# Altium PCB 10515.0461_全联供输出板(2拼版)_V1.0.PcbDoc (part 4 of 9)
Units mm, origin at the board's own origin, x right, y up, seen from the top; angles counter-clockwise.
Board outline 283.88 x 134.8 mm, 2 copper layers (Top Layer, Bottom Layer); 298 components, 0 nets, 1264 pads, 970 vias.
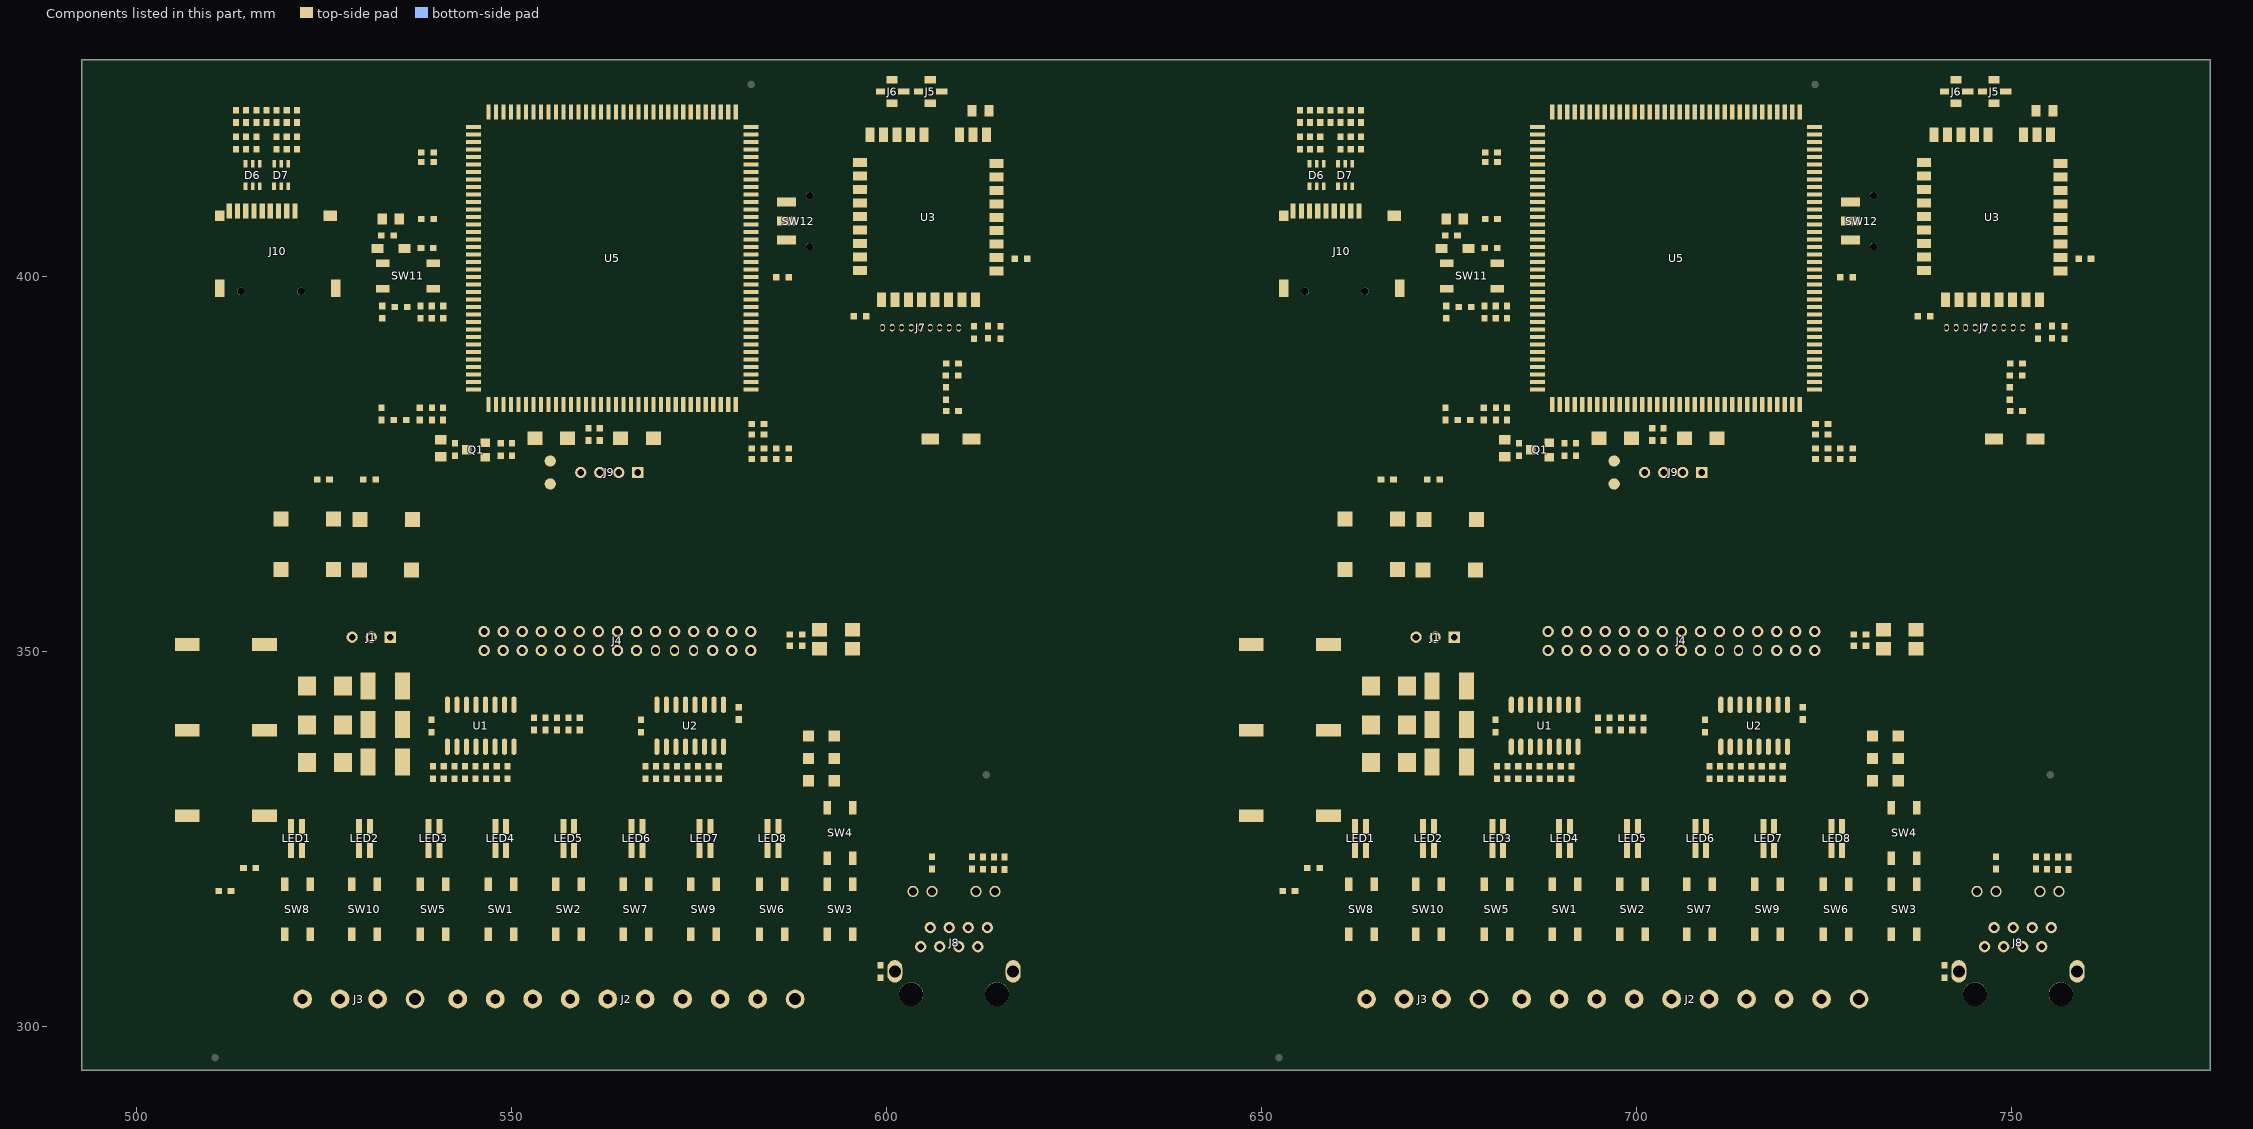
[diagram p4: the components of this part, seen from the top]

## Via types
v1: diameter 0.7, hole 0.4, Top Layer to Bottom Layer, tented both sides, 970 vias

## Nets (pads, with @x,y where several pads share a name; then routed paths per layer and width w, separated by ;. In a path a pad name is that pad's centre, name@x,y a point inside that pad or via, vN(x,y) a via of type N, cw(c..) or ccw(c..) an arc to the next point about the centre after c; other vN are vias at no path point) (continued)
copper on no net: (continued)
  Top Layer w0.3: 724.578,385.822 cw(c724.792,385.608) 724.792,385.91 cw(c724.792,386.212) 724.578,385.998 ; 724.578,386.822 cw(c724.792,386.608) 724.792,386.91 cw(c724.792,387.212) 724.578,386.998 ; 724.578,388.822 cw(c724.792,388.608) 724.792,388.91 cw(c724.792,389.212) 724.578,388.998 ; 724.578,389.822 cw(c724.792,389.608) 724.792,389.91 cw(c724.792,390.212) 724.578,389.998 ; 724.578,399.822 cw(c724.792,399.608) 724.792,399.91 cw(c724.792,400.212) 724.578,399.998 ; 724.578,406.822 cw(c724.792,406.608) 724.792,406.91 cw(c724.792,407.212) 724.578,406.998 ; 724.578,407.822 cw(c724.792,407.608) 724.792,407.91 cw(c724.792,408.212) 724.578,407.998 ; 724.677,303.604 724.677,305.94 725.084,306.347 733.247,306.347 735.273,308.373 739.083,308.373 741.016,310.306 741.016,336.751 740.508,337.259 731.815,337.259 731.46,337.614 ; 725.528,378.915 731.561,378.915 731.95,378.526 731.95,356.436 ; 725.528,380.312 731.815,380.312 732.577,379.55 732.577,355.547 ; 725.748,378.734 cw(c726.186,378.296) 726.186,378.915 cw(c726.186,379.534) 725.748,379.096 ; 725.748,380.131 cw(c726.186,379.693) 726.186,380.312 cw(c726.186,380.931) 725.748,380.493 ; 725.796,327.393 ccw(c725.369,327.82) 725.973,327.82 ccw(c726.577,327.82) 726.15,327.393 ; 726.426,399.91 cw(c726.426,399.154) 726.96,399.689 ; v1(726.611,312.243) 728.327,312.243 ; 726.619,399.91 ccw(c726.619,400.392) 726.96,400.051 ; v1@726.752,312.101 cw(c727.094,311.76) 727.094,312.243 cw(c727.094,312.726) v1@726.752,312.384 ; 727.256,327.368 ccw(c726.829,327.795) 727.433,327.795 ccw(c728.037,327.795) 727.61,327.368 ; 727.525,404.505 ccw(c726.757,403.737) 726.757,404.823 ccw(c726.757,405.909) 727.525,405.141 ; 727.525,409.585 ccw(c726.757,408.817) 726.757,409.903 ccw(c726.757,410.989) 727.525,410.221 ; 728.08,311.995 ccw(c727.482,311.398) 727.482,312.243 ccw(c727.482,313.088) 728.08,312.49 ; 728.479,350.277 ccw(c728.035,350.721) 728.663,350.721 ; 728.488,350.286 cw(c728.919,349.855) 728.919,350.465 ; 728.513,407.363 730.291,407.363 730.672,406.982 730.672,400.124 730.418,399.87 728.83,399.87 ; 729.05,399.689 cw(c729.488,399.251) 729.488,399.87 cw(c729.488,400.489) 729.05,400.051 ; 729.161,304.576 ccw(c728.707,305.433) 729.677,305.433 ; 729.302,304.311 ccw(c728.971,304.934) 729.677,304.934 ccw(c730.383,304.934) 730.052,304.311 ; 729.501,407.045 cw(c730.269,406.277) 730.269,407.363 cw(c730.269,408.449) 729.501,407.681 ; v1@729.642,377.758 ccw(c729.3,377.416) 729.3,377.899 ccw(c729.3,378.382) v1@729.642,378.04 ; 729.677,303.604 729.677,305.433 ; 730.193,304.576 cw(c730.647,305.433) 729.677,305.433 ; v1@730.72,390.678 753.532,390.678 754.119,390.678 754.421,390.98 754.421,393.33 ; v1@730.813,390.585 cw(c731.038,390.36) 731.038,390.678 ; v1@730.813,390.867 ccw(c731.272,391.326) 731.272,390.678 ; 731.148,338.169 cw(c730.811,337.614) 731.46,337.614 ; 731.207,332.168 cw(c731.023,331.772) 731.46,331.772 ; v1@731.42,355.66 ccw(c731.078,355.318) 731.078,355.801 ccw(c731.078,356.284) v1@731.42,355.942 ; v1@731.426,355.92 731.434,355.92 731.95,356.436 ; 731.46,332.712 731.46,331.772 ; 731.46,338.681 731.46,337.614 ; v1@731.546,356 ccw(c731.513,356.436) 731.95,356.436 ; v1@731.568,355.701 ccw(c731.538,356.113) 731.95,356.113 ; v1@731.627,355.99 ccw(c731.73,356.283) 731.95,356.063 ; 731.713,332.168 ccw(c731.896,331.772) 731.46,331.772 ; v1@731.758,355.834 cw(c732.436,355.95) 731.95,356.436 ; 731.772,338.169 ccw(c732.109,337.614) 731.46,337.614 ; 732.536,354.277 732.536,354.445 732.069,354.912 732.577,355.42 732.577,355.547 ; 732.577,354.912 732.577,355.547 ; 734.889,335.697 739.992,335.697 ; 734.889,338.681 736.108,338.681 ; 735.313,332.288 cw(c736.337,331.264) 736.337,332.712 cw(c736.337,334.161) 735.313,333.137 ; 735.313,335.273 cw(c736.337,334.248) 736.337,335.697 cw(c736.337,337.145) 735.313,336.121 ; 735.364,338.316 cw(c736.108,337.744) 736.108,338.681 ; 735.364,339.047 ccw(c736.108,339.619) 736.108,338.681 ; v1@735.484,392.518 ccw(c735.142,392.86) 735.625,392.86 ccw(c736.108,392.86) v1@735.766,392.518 ; v1(735.625,392.377) 735.625,403.807 736.189,404.371 738.336,404.371 ; 736.309,393.483 cw(c736.486,393.185) 736.731,393.43 ; v1@736.463,393.225 cw(c736.69,392.844) 737.003,393.158 ; 736.474,393.687 cw(c736.075,393.289) v1@736.609,393.107 ; v1@736.627,332.571 ccw(c736.285,332.23) 736.285,332.712 ccw(c736.285,333.195) v1@736.627,332.854 ; v1@736.63,393.302 cw(c736.967,393.774) 736.387,393.774 ; v1@736.655,392.998 cw(c736.997,392.656) 736.997,393.139 cw(c736.997,393.622) v1@736.655,393.28 ; v1@736.909,332.571 cw(c737.251,332.23) 737.251,332.712 cw(c737.251,333.195) v1@736.909,332.854 ; 737.276,393.139 737.022,393.139 736.387,393.774 ; 737.329,394.844 ccw(c736.891,395.282) 737.51,395.282 ccw(c738.13,395.282) 737.692,394.844 ; v1@737.389,395.411 cw(c737.094,395.116) 737.51,395.116 ; v1@737.389,395.693 ccw(c737.094,395.988) 737.51,395.988 ; 737.51,394.663 737.51,399.945 738.336,400.771 ; 737.51,395.022 cw(c738.06,395.022) v1@737.671,395.411 ; 737.51,396.082 ccw(c738.06,396.082) v1@737.671,395.693 ; 737.668,402.253 ccw(c736.9,401.485) 736.9,402.571 ccw(c736.9,403.657) 737.668,402.889 ; 737.668,404.053 ccw(c736.9,403.285) 736.9,404.371 ccw(c736.9,405.457) 737.668,404.689 ; 738.336,402.571 736.802,402.571 736.387,402.156 736.387,393.774 ; 739.054,335.697 ccw(c739.054,336.31) v1@739.488,335.876 ; 739.161,394.663 741.34,394.663 ; 739.238,335.697 cw(c739.238,335.344) v1@739.488,335.594 ; 739.381,394.482 cw(c739.819,394.044) 739.819,394.663 cw(c739.819,395.282) 739.381,394.844 ; v1@739.744,335.571 cw(c739.927,335.307) 740.154,335.535 ; v1@739.778,335.601 cw(c739.992,335.409) 739.992,335.697 ; v1@739.813,335.815 ccw(c739.992,335.893) 739.992,335.697 ; 740.868,396.203 cw(c740.1,395.435) 741.186,395.435 cw(c742.272,395.435) 741.504,396.203 ; 741.042,308.151 cw(c741.612,308.151) 741.209,308.553 ; 741.086,308.407 ccw(c741.086,309.118) 741.589,308.615 ; 741.186,396.871 741.186,394.817 741.34,394.663 ; 741.219,306.719 ccw(c741.432,307.068) 741.721,306.779 ; 741.234,393.033 ccw(c740.978,392.777) 740.978,393.139 ccw(c740.978,393.501) 741.234,393.245 ; 741.267,306.28 cw(c741.705,305.842) 741.705,306.462 cw(c741.705,307.081) 741.267,306.643 ; 741.339,306.456 cw(c741.721,306.391) 741.721,306.779 ; 741.34,393.139 v1@736.768,393.139 ; 741.403,306.779 741.721,306.779 ; 741.497,308.523 ccw(c741.869,308.151) 741.342,308.151 cw(c742.636,308.151) 741.721,309.065 ; 741.749,306.807 cw(c742.386,306.169) 743.009,306.821 ; 741.755,306.496 cw(c742.342,305.908) 742.828,306.582 ; 741.966,307.024 cw(c742.598,306.391) 743.216,307.038 ; 742.126,306.841 cw(c741.721,306.867) 741.721,306.462 ; 742.227,307.285 741.721,306.779 ; 742.316,393.687 cw(c741.967,393.339) 742.46,393.339 ; 742.356,309.383 741.086,308.113 741.086,308.43 742.102,309.446 744.388,309.446 744.642,309.192 750.865,309.192 751.504,309.831 751.504,310.585 ; 742.367,306.19 ccw(c741.721,305.558) 741.721,306.462 ; 742.61,393.139 742.61,393.393 741.34,394.663 ; 742.661,396.202 cw(c741.899,395.437) 742.979,395.437 ; 742.979,396.871 742.979,395.437 ; 743.297,396.202 ccw(c744.059,395.437) 742.979,395.437 ; 743.774,393.445 ccw(c743.518,393.701) 743.88,393.701 ccw(c744.242,393.701) 743.986,393.445 ; 743.88,393.139 743.88,394.536 742.979,395.437 ; 744.454,396.203 cw(c743.685,395.435) 744.772,395.435 cw(c745.858,395.435) 745.09,396.203 ; 744.772,396.871 744.772,395.295 745.15,394.917 745.15,393.139 ; 745.044,393.445 ccw(c744.788,393.701) 745.15,393.701 ccw(c745.512,393.701) 745.256,393.445 ; 746.246,396.203 cw(c745.827,395.784) 746.42,395.784 ; 746.314,393.445 ccw(c746.058,393.701) 746.42,393.701 ccw(c746.782,393.701) 746.526,393.445 ; 746.42,393.139 746.42,396.726 ; 746.42,395.086 cw(c748,395.086) 746.883,396.203 ; 746.42,395.81 cw(c747.276,395.81) 746.671,396.415 ; 746.424,310.585 746.424,315.165 747.182,315.923 748.96,315.923 749.468,316.431 v1(749.468,339.418) ; 747.27,313.549 ccw(c746.245,314.574) 747.694,314.574 ccw(c749.143,314.574) 748.118,313.549 ; 747.52,318.379 ccw(c746.495,319.404) 747.944,319.404 ccw(c749.392,319.403) 748.368,318.379 ; 747.584,393.445 ccw(c747.328,393.701) 747.69,393.701 ccw(c748.052,393.701) 747.796,393.445 ; 747.69,393.139 747.69,394.79 748.357,395.457 ; 747.694,313.125 747.694,314.657 748.198,315.161 749.468,315.161 750.23,315.923 v1(750.23,338.783) ; 747.763,320.72 cw(c747.325,320.282) 747.944,320.282 cw(c748.563,320.282) 748.125,320.72 ; 747.944,317.955 747.944,320.94 ; 747.944,322.591 v1@748.769,322.591 ; 748.044,396.198 cw(c747.326,395.457) 748.357,395.457 ; 748.07,322.591 cw(c748.07,321.891) v1@748.565,322.386 ; 748.125,322.409 cw(c748.563,321.971) 748.563,322.591 cw(c748.563,323.21) 748.125,322.772 ; v1@748.311,325.716 ccw(c747.969,326.058) 748.452,326.058 ccw(c748.935,326.058) v1@748.593,325.716 ; 748.357,396.871 748.357,395.457 ; 748.671,396.198 ccw(c749.389,395.457) 748.357,395.457 ; v1@749.268,341.577 ccw(c748.785,341.577) 749.127,341.918 ccw(c749.468,342.26) v1@749.468,341.777 ; v1@749.327,339.277 cw(c748.985,338.935) 749.468,338.935 cw(c749.951,338.935) v1@749.609,339.277 ; 749.832,396.203 cw(c748.871,395.242) 750.23,395.242 ; v1@750.03,342.212 ccw(c749.547,342.212) 749.889,342.553 ccw(c750.23,342.895) v1@750.23,342.412 ; v1@750.089,338.642 cw(c749.747,338.3) 750.23,338.3 cw(c750.713,338.3) v1@750.371,338.642 ; 750.124,393.445 ccw(c749.868,393.701) 750.23,393.701 ccw(c750.592,393.701) 750.336,393.445 ; 750.15,396.871 750.23,396.791 750.23,393.139 ; 750.23,395.627 cw(c751.044,395.627) 750.468,396.203 ; v1(752.389,323.797) 755.818,323.797 756.199,323.416 756.199,322.541 757.596,322.541 ; v1@752.45,322.588 753.286,322.588 ; v1@752.53,322.386 cw(c753.02,321.896) 753.02,322.588 ; v1@752.53,323.656 cw(c752.872,323.314) 752.872,323.797 cw(c752.872,324.28) v1@752.53,323.938 ; v1(752.897,324.94) 758.485,324.94 758.866,324.559 758.866,318.717 758.104,317.955 756.334,317.955 ; v1@753.038,324.799 cw(c753.38,324.457) 753.38,324.94 cw(c753.38,325.423) v1@753.038,325.081 ; 753.104,320.718 cw(c752.667,320.28) 753.286,320.28 cw(c753.905,320.28) 753.467,320.718 ; 753.104,322.407 ccw(c752.667,321.969) 752.667,322.588 ccw(c752.667,323.207) 753.104,322.77 ; v1@753.137,319.747 ccw(c752.776,320.108) 753.286,320.108 ; v1@753.286,319.614 753.286,320.937 756.151,320.937 ; 753.286,320.07 ccw(c753.742,320.07) v1@753.419,319.747 ; 753.331,322.543 754.725,322.543 ; 753.386,418.871 753.386,418.989 ; 753.467,320.756 cw(c753.905,320.318) 753.905,320.937 cw(c753.905,321.556) 753.467,321.119 ; 753.467,322.369 cw(c753.887,321.948) 753.887,322.543 ; 753.467,322.731 ccw(c753.922,323.186) 753.922,322.543 ; 753.62,311.009 ccw(c752.595,312.034) 754.044,312.034 ccw(c755.492,312.034) 754.468,311.009 ; 753.89,318.821 ccw(c754.384,318.328) 753.794,317.955 753.794,318.725 754.421,319.352 ; 754.048,318.115 cw(c754.709,318.533) 754.156,319.087 ; 754.089,320.937 cw(c754.089,320.294) 754.544,320.749 ; 754.123,320.937 ccw(c754.123,321.532) 754.544,321.111 ; 754.301,318.276 cw(c755.034,318.739) 754.421,319.352 ; 754.544,322.362 ccw(c754.106,321.924) 754.106,322.543 ccw(c754.106,323.162) 754.544,322.724 ; 754.906,320.749 cw(c755.361,320.294) 755.361,320.937 ; 754.906,321.111 ccw(c755.327,321.532) 755.327,320.937 ; 755.557,320.937 cw(c755.557,320.286) 756.018,320.746 ; 755.603,320.937 ccw(c755.603,321.524) 756.018,321.109 ; 756.018,322.76 ccw(c755.58,323.198) 756.199,323.198 ccw(c756.818,323.198) 756.38,322.76 ; 756.38,322.359 cw(c756.818,321.922) 756.818,322.541 cw(c756.818,323.16) 756.38,322.722 ; 756.536,404.271 756.58,404.271 ; 757.269,393.148 cw(c757.707,392.71) 757.707,393.33 cw(c757.707,393.949) 757.269,393.511 ; 757.269,393.186 cw(c758.075,392.381) 758.075,393.52 ; 757.415,320.67 cw(c756.977,320.232) 757.596,320.232 cw(c758.215,320.232) 757.777,320.67 ; 757.415,322.359 ccw(c756.977,321.922) 756.977,322.541 ccw(c756.977,323.16) 757.415,322.722 ; 757.596,320.89 757.596,319.606 757.342,319.352 754.421,319.352 ; v1@758.463,404.293 v1(758.463,404.315) ; 758.805,402.471 758.943,402.333 759.247,402.029 759.247,393.849 758.727,393.33 756.707,393.33 756.897,393.33 757.088,393.52 758.612,393.52 758.993,393.901 758.993,402.283 ; 758.993,401.683 cw(c759.655,401.683) 759.187,402.152 ; 758.993,401.745 ccw(c758.417,401.745) 758.824,402.152 cw(c757.804,401.131) 759.247,401.131 ; 759.037,402.364 cw(c758.528,401.856) 759.247,401.856 ; 544.576,383.36 544.576,384.63 544.856,384.91 544.865,384.91 ; 558.8,314.272 558.9,314.272 ; 567.39,327.688 567.771,328.069 ; 587.777,305.433 588.137,305.793 591.576,305.793 593.602,307.819 597.412,307.819 599.67,310.077 599.67,337.57 599.392,337.848 595.041,337.848 594.208,338.681 ; 590.05,356.063 590.05,356.436 ; 594.487,393.52 ccw(c594.672,393.52) 594.644,393.337 cw(c594.672,393.52) 594.487,393.52 ; 594.487,393.52 594.487,393.139 v1@594.868,393.139 ; 594.487,393.52 594.487,393.774 ; 594.487,393.52 v1@594.868,393.139 ; 599.821,306.462 600.644,307.285 601.074,307.285 600.25,306.462 599.821,306.462 ; 599.821,306.462 599.186,306.462 599.504,306.462 599.821,306.779 ; 686.476,383.36 686.476,384.63 686.756,384.91 686.765,384.91 ; 700.7,314.272 700.8,314.272 ; 709.29,327.688 709.671,328.069 ; 729.677,305.433 730.037,305.793 733.476,305.793 735.502,307.819 739.312,307.819 741.57,310.077 741.57,337.57 741.292,337.848 736.941,337.848 736.108,338.681 ; 731.95,356.063 731.95,356.436 ; 736.387,393.52 ccw(c736.572,393.52) 736.544,393.337 cw(c736.572,393.52) 736.387,393.52 ; 736.387,393.52 736.387,393.139 v1@736.768,393.139 ; 736.387,393.52 736.387,393.774 ; 736.387,393.52 v1@736.768,393.139 ; 741.721,306.462 742.544,307.285 742.974,307.285 742.15,306.462 741.721,306.462 ; 741.721,306.462 741.086,306.462 741.403,306.462 741.721,306.779
  Top Layer w0.4: 550.037,377.709 550.865,378.537 550.865,382.91 ; 550.037,377.953 ccw(c550.037,378.543) 550.454,378.126 ; 550.243,377.747 cw(c550.65,377.747) 550.362,378.034 ; 691.937,377.709 692.765,378.537 692.765,382.91 ; 691.937,377.953 ccw(c691.937,378.543) 692.354,378.126 ; 692.143,377.747 cw(c692.55,377.747) 692.262,378.034
  Top Layer w0.45: 519.491,311.648 cw(c519.022,311.179) 519.686,311.179 cw(c520.35,311.179) 519.88,311.648 ; 519.491,312.837 ccw(c519.022,313.307) 519.686,313.307 ccw(c520.35,313.307) 519.88,312.837 ; 519.491,318.348 cw(c519.022,317.879) 519.686,317.879 cw(c520.35,317.879) 519.88,318.348 ; 519.686,318.943 519.686,312.243 519.686,309.698 520.192,309.192 582.041,309.192 583.027,310.178 583.027,310.208 ; 522.891,312.837 ccw(c522.422,313.307) 523.086,313.307 ccw(c523.75,313.307) 523.28,312.837 ; 522.891,318.348 cw(c522.422,317.879) 523.086,317.879 cw(c523.75,317.879) 523.28,318.348 ; 523.086,312.243 523.086,318.943 ; 528.438,312.837 ccw(c527.969,313.307) 528.633,313.307 ccw(c529.297,313.307) 528.827,312.837 ; 528.438,318.348 cw(c527.969,317.879) 528.633,317.879 cw(c529.297,317.879) 528.827,318.348 ; 528.633,312.878 528.633,318.943 ; 531.838,311.648 cw(c531.369,311.179) 532.033,311.179 cw(c532.697,311.179) 532.227,311.648 ; 531.838,312.837 ccw(c531.369,313.307) 532.033,313.307 ccw(c532.697,313.307) 532.227,312.837 ; 531.838,318.348 cw(c531.369,317.879) 532.033,317.879 cw(c532.697,317.879) 532.227,318.348 ; 532.033,318.943 532.033,312.243 532.033,310.462 ; 532.599,309.896 532.033,310.462 ; 537.589,312.837 ccw(c537.119,313.307) 537.783,313.307 ccw(c538.447,313.307) 537.978,312.837 ; 537.589,318.348 cw(c537.119,317.879) 537.783,317.879 cw(c538.447,317.879) 537.978,318.348 ; 537.783,312.243 537.783,318.943 537.783,319.544 ; 537.783,313.821 cw(c538.296,313.821) v1@537.933,314.184 ; 537.783,314.723 ccw(c538.296,314.723) v1@537.933,314.36 ; 539.292,339.189 539.521,339.418 v1(540.258,339.418) ; 539.292,340.84 v1(541.401,340.84) 541.401,342.847 ; 539.42,339.099 cw(c540.19,338.33) v1@540.19,339.418 ; 539.42,340.712 cw(c539.73,340.402) 539.73,340.84 cw(c539.73,341.278) 539.42,340.969 ; 540.843,394.384 542.265,394.384 542.791,394.91 ; 540.968,395.91 542.671,395.91 ; 540.971,394.255 cw(c541.281,393.946) 541.281,394.384 cw(c541.281,394.822) 540.971,394.512 ; 540.971,394.293 cw(c541.833,393.432) 541.833,394.65 ; 540.971,395.944 cw(c541.682,395.233) 541.682,396.239 ; 540.971,396.125 ccw(c541.49,396.643) 541.49,395.91 ; 540.989,312.837 ccw(c540.519,313.307) 541.183,313.307 ccw(c541.847,313.307) 541.378,312.837 ; 540.989,318.348 cw(c540.519,317.879) 541.183,317.879 cw(c541.847,317.879) 541.378,318.348 ; 541.047,396.239 542.111,396.239 ; 541.11,394.65 541.922,394.65 ; 541.183,312.243 541.183,318.943 ; 541.655,394.384 541.922,394.65 ; 541.782,395.91 542.111,396.239 ; 542.163,395.91 542.267,395.91 542.671,396.314 ; 543.941,342.847 v1(543.941,344.371) ; 544.865,394.91 542.791,394.91 ; 544.865,395.91 542.671,395.91 ; 544.865,396.91 542.759,396.91 542.671,396.822 ; 545.211,342.847 v1(545.211,339.418) v1(550.291,339.418) 550.291,337.259 ; 546.638,312.837 ccw(c546.168,313.307) 546.832,313.307 ccw(c547.496,313.307) 547.027,312.837 ; 546.638,318.348 cw(c546.168,317.879) 546.832,317.879 cw(c547.496,317.879) 547.027,318.348 ; 546.832,311.381 547.497,310.716 548.005,310.716 ; 546.832,311.568 cw(c546.832,310.792) 547.38,311.341 ; 546.832,318.943 546.832,312.243 546.832,311.889 548.005,310.716 ; 547.09,311.748 ccw(c547.804,311.485) 547.266,310.947 ; 547.107,311.843 ccw(c547.66,311.843) 547.269,311.452 ; v1(549.021,340.815) 549.021,342.847 ; 550.038,312.837 ccw(c549.568,313.307) 550.232,313.307 ccw(c550.896,313.307) 550.427,312.837 ; 550.038,318.348 cw(c549.568,317.879) 550.232,317.879 cw(c550.896,317.879) 550.427,318.348 ; 550.232,312.243 550.232,318.531 ; 555.686,312.837 ccw(c555.217,313.307) 555.881,313.307 ccw(c556.545,313.307) 556.075,312.837 ; 555.686,318.348 cw(c555.217,317.879) 555.881,317.879 cw(c556.545,317.879) 556.075,318.348 ; 555.686,319.537 ccw(c555.217,320.007) 555.881,320.007 ccw(c556.545,320.007) 556.075,319.537 ; 555.881,312.243 555.881,318.943 555.881,320.878 556.387,321.384 590.296,321.384 590.804,321.892 590.804,330.02 591.439,330.655 595.249,330.655 595.476,330.428 595.476,329.103 595.476,322.403 595.476,318.943 595.476,312.243 ; 557.428,378.09 560.197,378.09 560.197,374.851 559.181,373.835 ; 557.687,378.566 ccw(c558.838,379.717) 558.838,378.09 ; 558.005,377.93 cw(c558.391,377.544) 558.391,378.09 ; 558.005,378.884 ccw(c559.924,380.803) 559.924,378.09 ; 559.054,341.133 559.371,340.815 v1(560.07,340.815) cw(c560.07,341.984) 559.19,341.214 ; 559.086,312.837 ccw(c558.617,313.307) 559.281,313.307 ccw(c559.945,313.307) 559.475,312.837 ; 559.086,318.348 cw(c558.617,317.879) 559.281,317.879 cw(c559.945,317.879) 559.475,318.348 ; 559.181,374.36 ccw(c559.181,375.627) 560.077,374.731 ccw(c560.973,373.835) 559.706,373.835 ; 559.281,312.243 559.281,314.272 559.281,318.943 ; 560.069,377.923 cw(c559.759,377.613) 560.197,377.613 cw(c560.635,377.613) 560.325,377.923 ; 560.069,377.961 ccw(c559.759,377.652) 559.759,378.09 ccw(c559.759,378.527) 560.069,378.218 ; v1@560.07,340.69 cw(c560.07,339.775) 560.717,340.422 ; v1@560.324,340.815 560.705,340.434 v1(560.705,337.132) ; 561.593,377.923 cw(c561.283,377.613) 561.721,377.613 cw(c562.159,377.613) 561.849,377.923 ; 561.721,373.835 561.721,378.09 564.172,378.09 564.49,378.407 ; 561.849,377.961 cw(c562.159,377.652) 562.159,378.09 cw(c562.159,378.527) 561.849,378.218 ; 561.994,378.09 ccw(c561.994,380.803) 563.913,378.884 ; 563.08,378.09 ccw(c563.08,379.717) 564.231,378.566 ; 563.527,378.09 cw(c563.527,377.544) 563.913,377.93 ; 564.16,310.869 ccw(c563.211,311.818) 564.553,311.839 ; 564.633,311.648 cw(c564.164,311.179) 564.828,311.179 cw(c565.492,311.179) 565.022,311.648 ; 564.633,312.837 ccw(c564.164,313.307) 564.828,313.307 ccw(c565.492,313.307) 565.022,312.837 ; 564.633,318.348 cw(c564.164,317.879) 564.828,317.879 cw(c565.492,317.879) 565.022,318.348 ; 564.769,311.478 564.007,310.716 ; 564.828,318.943 564.828,312.243 ; 565.022,312.048 cw(c565.492,311.579) 565.492,312.243 cw(c565.492,312.907) 565.022,312.437 ; v1(566.417,312.243) 564.828,312.243 ; 567.232,340.84 v1(569.341,340.84) 569.341,342.847 ; 567.36,339.099 cw(c568.13,338.33) v1@568.13,339.418 ; 567.36,340.712 cw(c567.67,340.402) 567.67,340.84 cw(c567.67,341.278) 567.36,340.969 ; 567.461,339.418 v1(568.325,339.418) ; 567.662,309.896 568.228,310.462 ; 568.033,311.648 cw(c567.564,311.179) 568.228,311.179 cw(c568.892,311.179) 568.422,311.648 ; 568.033,312.837 ccw(c567.564,313.307) 568.228,313.307 ccw(c568.892,313.307) 568.422,312.837 ; 568.033,318.348 cw(c567.564,317.879) 568.228,317.879 cw(c568.892,317.879) 568.422,318.348 ; 568.228,309.993 568.228,310.462 ; 568.228,318.943 568.228,312.243 568.228,310.462 ; 568.96,309.896 568.394,310.462 568.228,310.462 ; 573.151,342.847 v1(573.151,339.418) 578.231,339.418 ; 573.682,312.837 ccw(c573.213,313.307) 573.877,313.307 ccw(c574.541,313.307) 574.071,312.837 ; 573.682,318.348 cw(c573.213,317.879) 573.877,317.879 cw(c574.541,317.879) 574.071,318.348 ; 573.877,312.243 573.877,318.943 ; 576.961,342.847 v1(576.961,340.815) 580.199,340.815 ; 577.082,311.648 cw(c576.613,311.179) 577.277,311.179 cw(c577.941,311.179) 577.471,311.648 ; 577.082,312.837 ccw(c576.613,313.307) 577.277,313.307 ccw(c577.941,313.307) 577.471,312.837 ; 577.082,318.348 cw(c576.613,317.879) 577.277,317.879 cw(c577.941,317.879) 577.471,318.348 ; 577.277,319.618 ccw(c577.277,320.417) 577.842,319.852 ; 577.552,319.343 cw(c578.08,319.343) 577.706,319.716 ; 578.231,337.259 578.231,339.418 ; 578.231,342.847 v1(578.993,342.847) ; 579.764,340.815 ccw(c579.764,341.34) 580.135,340.969 ; 581.66,309.192 583.027,310.559 583.027,310.716 ; v1(581.787,339.418) 578.231,339.418 ; v1(582.676,343.101) 582.676,333.576 583.54,332.712 589.56,332.712 ; 582.833,311.648 cw(c582.363,311.179) 583.027,311.179 cw(c583.691,311.179) 583.222,311.648 ; 582.833,312.837 ccw(c582.363,313.307) 583.027,313.307 ccw(c583.691,313.307) 583.222,312.837 ; 582.833,318.348 cw(c582.363,317.879) 583.027,317.879 cw(c583.691,317.879) 583.222,318.348 ; 583.027,318.943 583.027,312.243 583.027,310.716 ; 583.565,342.265 cw(c584.084,342.265) v1@583.717,342.632 ; v1@583.565,342.72 583.565,336.116 583.984,335.697 589.56,335.697 ; v1(584.581,343.101) 584.581,339.037 585.216,338.402 589.534,338.402 ; 586.233,312.837 ccw(c585.763,313.307) 586.427,313.307 ccw(c587.091,313.307) 586.622,312.837 ; 586.233,318.348 cw(c585.763,317.879) 586.427,317.879 cw(c587.091,317.879) 586.622,318.348 ; 586.427,312.243 586.427,318.943 ; 589.189,332.341 ccw(c588.292,331.445) 588.292,332.712 ccw(c588.292,333.98) 589.189,333.084 ; 589.189,335.326 ccw(c588.292,334.429) 588.292,335.697 ccw(c588.292,336.964) 589.189,336.068 ; 590.492,310.912 cw(c592.076,309.327) 592.076,311.568 ccw(c592.076,310.86) 591.576,311.361 ; 591.26,311.68 cw(c592.076,310.864) 592.076,312.018 ; 591.439,321.13 ccw(c590.567,322.003) 591.801,322.003 ; 591.619,311.404 ccw(c591.18,311.843) 591.801,311.843 ; 591.823,312.243 589.788,310.208 ; 591.881,312.837 ccw(c591.412,313.307) 592.076,313.307 ccw(c592.74,313.307) 592.27,312.837 ; 591.881,318.348 cw(c591.412,317.879) 592.076,317.879 cw(c592.74,317.879) 592.27,318.348 ; 591.881,322.997 ccw(c591.412,323.467) 592.076,323.467 ccw(c592.74,323.467) 592.27,322.997 ; 591.881,328.508 cw(c591.412,328.039) 592.076,328.039 cw(c592.74,328.039) 592.27,328.508 ; 592.076,318.943 592.076,312.243 592.076,311.861 590.423,310.208 589.788,310.208 ; 592.076,329.103 592.076,322.403 592.076,321.767 590.804,320.495 578.485,320.495 577.277,319.287 577.277,318.943 577.277,312.243 577.277,310.651 576.522,309.896 532.188,309.896 532.033,310.051 532.033,310.462 ; 595.281,312.837 ccw(c594.812,313.307) 595.476,313.307 ccw(c596.14,313.307) 595.67,312.837 ; 595.281,318.348 cw(c594.812,317.879) 595.476,317.879 cw(c596.14,317.879) 595.67,318.348 ; 595.281,319.537 ccw(c594.812,320.007) 595.476,320.007 ccw(c596.14,320.007) 595.67,319.537 ; 595.281,321.808 cw(c594.812,321.339) 595.476,321.339 cw(c596.14,321.339) 595.67,321.808 ; 595.281,322.997 ccw(c594.812,323.467) 595.476,323.467 ccw(c596.14,323.467) 595.67,322.997 ; 595.281,328.508 cw(c594.812,328.039) 595.476,328.039 cw(c596.14,328.039) 595.67,328.508 ; 595.281,329.697 ccw(c594.812,330.167) 595.476,330.167 ccw(c596.14,330.167) 595.67,329.697 ; 661.391,311.648 cw(c660.922,311.179) 661.586,311.179 cw(c662.25,311.179) 661.78,311.648 ; 661.391,312.837 ccw(c660.922,313.307) 661.586,313.307 ccw(c662.25,313.307) 661.78,312.837 ; 661.391,318.348 cw(c660.922,317.879) 661.586,317.879 cw(c662.25,317.879) 661.78,318.348 ; 661.586,318.943 661.586,312.243 661.586,309.698 662.092,309.192 723.941,309.192 724.927,310.178 724.927,310.208 ; 664.791,312.837 ccw(c664.322,313.307) 664.986,313.307 ccw(c665.65,313.307) 665.18,312.837 ; 664.791,318.348 cw(c664.322,317.879) 664.986,317.879 cw(c665.65,317.879) 665.18,318.348 ; 664.986,312.243 664.986,318.943 ; 670.338,312.837 ccw(c669.869,313.307) 670.533,313.307 ccw(c671.197,313.307) 670.727,312.837 ; 670.338,318.348 cw(c669.869,317.879) 670.533,317.879 cw(c671.197,317.879) 670.727,318.348 ; 670.533,312.878 670.533,318.943 ; 673.738,311.648 cw(c673.269,311.179) 673.933,311.179 cw(c674.597,311.179) 674.127,311.648 ; 673.738,312.837 ccw(c673.269,313.307) 673.933,313.307 ccw(c674.597,313.307) 674.127,312.837 ; 673.738,318.348 cw(c673.269,317.879) 673.933,317.879 cw(c674.597,317.879) 674.127,318.348 ; 673.933,318.943 673.933,312.243 673.933,310.462 ; 674.499,309.896 673.933,310.462 ; 679.489,312.837 ccw(c679.019,313.307) 679.683,313.307 ccw(c680.347,313.307) 679.878,312.837 ; 679.489,318.348 cw(c679.019,317.879) 679.683,317.879 cw(c680.347,317.879) 679.878,318.348 ; 679.683,312.243 679.683,318.943 679.683,319.544 ; 679.683,313.821 cw(c680.196,313.821) v1@679.833,314.184 ; 679.683,314.723 ccw(c680.196,314.723) v1@679.833,314.36 ; 681.192,339.189 681.421,339.418 v1(682.158,339.418) ; 681.192,340.84 v1(683.301,340.84) 683.301,342.847 ; 681.32,339.099 cw(c682.09,338.33) v1@682.09,339.418 ; 681.32,340.712 cw(c681.63,340.402) 681.63,340.84 cw(c681.63,341.278) 681.32,340.969 ; 682.743,394.384 684.165,394.384 684.691,394.91 ; 682.868,395.91 684.571,395.91 ; 682.871,394.255 cw(c683.181,393.946) 683.181,394.384 cw(c683.181,394.822) 682.871,394.512 ; 682.871,394.293 cw(c683.733,393.432) 683.733,394.65 ; 682.871,395.944 cw(c683.582,395.233) 683.582,396.239 ; 682.871,396.125 ccw(c683.39,396.643) 683.39,395.91 ; 682.889,312.837 ccw(c682.419,313.307) 683.083,313.307 ccw(c683.747,313.307) 683.278,312.837 ; 682.889,318.348 cw(c682.419,317.879) 683.083,317.879 cw(c683.747,317.879) 683.278,318.348 ; 682.947,396.239 684.011,396.239 ; 683.01,394.65 683.822,394.65 ; 683.083,312.243 683.083,318.943 ; 683.555,394.384 683.822,394.65 ; 683.682,395.91 684.011,396.239 ; 684.063,395.91 684.167,395.91 684.571,396.314 ; 685.841,342.847 v1(685.841,344.371) ; 686.765,394.91 684.691,394.91 ; 686.765,395.91 684.571,395.91 ; 686.765,396.91 684.659,396.91 684.571,396.822 ; 687.111,342.847 v1(687.111,339.418) v1(692.191,339.418) 692.191,337.259 ; 688.538,312.837 ccw(c688.068,313.307) 688.732,313.307 ccw(c689.396,313.307) 688.926,312.837 ; 688.538,318.348 cw(c688.068,317.879) 688.732,317.879 cw(c689.396,317.879) 688.926,318.348 ; 688.732,311.381 689.397,310.716 689.905,310.716 ; 688.732,311.568 cw(c688.732,310.792) 689.28,311.341 ; 688.732,318.943 688.732,312.243 688.732,311.889 689.905,310.716 ; 688.99,311.748 ccw(c689.704,311.485) 689.166,310.947 ; 689.007,311.843 ccw(c689.56,311.843) 689.169,311.452 ; v1(690.921,340.815) 690.921,342.847 ; 691.938,312.837 ccw(c691.468,313.307) 692.132,313.307 ccw(c692.796,313.307) 692.326,312.837 ; 691.938,318.348 cw(c691.468,317.879) 692.132,317.879 cw(c692.796,317.879) 692.326,318.348 ; 692.132,312.243 692.132,318.531 ; 697.586,312.837 ccw(c697.117,313.307) 697.781,313.307 ccw(c698.445,313.307) 697.975,312.837 ; 697.586,318.348 cw(c697.117,317.879) 697.781,317.879 cw(c698.445,317.879) 697.975,318.348 ; 697.586,319.537 ccw(c697.117,320.007) 697.781,320.007 ccw(c698.445,320.007) 697.975,319.537 ; 697.781,312.243 697.781,318.943 697.781,320.878 698.287,321.384 732.196,321.384 732.704,321.892 732.704,330.02 733.339,330.655 737.149,330.655 737.376,330.428 737.376,329.103 737.376,322.403 737.376,318.943 737.376,312.243 ; 699.328,378.09 702.097,378.09 702.097,374.851 701.081,373.835 ; 699.587,378.566 ccw(c700.738,379.717) 700.738,378.09 ; 699.905,377.93 cw(c700.291,377.544) 700.291,378.09 ; 699.905,378.884 ccw(c701.824,380.803) 701.824,378.09 ; 700.954,341.133 701.271,340.815 v1(701.97,340.815) cw(c701.97,341.984) 701.09,341.214 ; 700.986,312.837 ccw(c700.517,313.307) 701.181,313.307 ccw(c701.845,313.307) 701.375,312.837 ; 700.986,318.348 cw(c700.517,317.879) 701.181,317.879 cw(c701.845,317.879) 701.375,318.348 ; 701.081,374.36 ccw(c701.081,375.627) 701.977,374.731 ccw(c702.873,373.835) 701.606,373.835 ; 701.181,312.243 701.181,314.272 701.181,318.943 ; 701.969,377.923 cw(c701.659,377.613) 702.097,377.613 cw(c702.535,377.613) 702.225,377.923 ; 701.969,377.961 ccw(c701.659,377.652) 701.659,378.09 ccw(c701.659,378.527) 701.969,378.218 ; v1@701.97,340.69 cw(c701.97,339.775) 702.617,340.422 ; v1@702.224,340.815 702.605,340.434 v1(702.605,337.132) ; 703.493,377.923 cw(c703.183,377.613) 703.621,377.613 cw(c704.059,377.613) 703.749,377.923 ; 703.621,373.835 703.621,378.09 706.072,378.09 706.39,378.407 ; 703.749,377.961 cw(c704.059,377.652) 704.059,378.09 cw(c704.059,378.527) 703.749,378.218 ; 703.894,378.09 ccw(c703.894,380.803) 705.813,378.884 ; 704.98,378.09 ccw(c704.98,379.717) 706.131,378.566 ; 705.427,378.09 cw(c705.427,377.544) 705.813,377.93 ; 706.06,310.869 ccw(c705.111,311.818) 706.453,311.839 ; 706.533,311.648 cw(c706.064,311.179) 706.728,311.179 cw(c707.392,311.179) 706.922,311.648 ; 706.533,312.837 ccw(c706.064,313.307) 706.728,313.307 ccw(c707.392,313.307) 706.922,312.837 ; 706.533,318.348 cw(c706.064,317.879) 706.728,317.879 cw(c707.392,317.879) 706.922,318.348 ; 706.669,311.478 705.907,310.716 ; 706.728,318.943 706.728,312.243 ; 706.922,312.048 cw(c707.392,311.579) 707.392,312.243 cw(c707.392,312.907) 706.922,312.437 ; v1(708.317,312.243) 706.728,312.243 ; 709.132,340.84 v1(711.241,340.84) 711.241,342.847 ; 709.26,339.099 cw(c710.03,338.33) v1@710.03,339.418 ; 709.26,340.712 cw(c709.57,340.402) 709.57,340.84 cw(c709.57,341.278) 709.26,340.969 ; 709.361,339.418 v1(710.225,339.418) ; 709.562,309.896 710.128,310.462 ; 709.933,311.648 cw(c709.464,311.179) 710.128,311.179 cw(c710.792,311.179) 710.322,311.648 ; 709.933,312.837 ccw(c709.464,313.307) 710.128,313.307 ccw(c710.792,313.307) 710.322,312.837 ; 709.933,318.348 cw(c709.464,317.879) 710.128,317.879 cw(c710.792,317.879) 710.322,318.348 ; 710.128,309.993 710.128,310.462 ; 710.128,318.943 710.128,312.243 710.128,310.462 ; 710.86,309.896 710.294,310.462 710.128,310.462 ; 715.051,342.847 v1(715.051,339.418) 720.131,339.418 ; 715.582,312.837 ccw(c715.113,313.307) 715.777,313.307 ccw(c716.441,313.307) 715.971,312.837 ; 715.582,318.348 cw(c715.113,317.879) 715.777,317.879 cw(c716.441,317.879) 715.971,318.348 ; 715.777,312.243 715.777,318.943 ; 718.861,342.847 v1(718.861,340.815) 722.099,340.815 ; 718.982,311.648 cw(c718.513,311.179) 719.177,311.179 cw(c719.841,311.179) 719.371,311.648 ; 718.982,312.837 ccw(c718.513,313.307) 719.177,313.307 ccw(c719.841,313.307) 719.371,312.837 ; 718.982,318.348 cw(c718.513,317.879) 719.177,317.879 cw(c719.841,317.879) 719.371,318.348 ; 719.177,319.618 ccw(c719.177,320.417) 719.742,319.852 ; 719.452,319.343 cw(c719.98,319.343) 719.606,319.716 ; 720.131,337.259 720.131,339.418 ; 720.131,342.847 v1(720.893,342.847) ; 721.664,340.815 ccw(c721.664,341.34) 722.035,340.969 ; 723.56,309.192 724.927,310.559 724.927,310.716 ; v1(723.687,339.418) 720.131,339.418 ; v1(724.576,343.101) 724.576,333.576 725.44,332.712 731.46,332.712 ; 724.733,311.648 cw(c724.263,311.179) 724.927,311.179 cw(c725.591,311.179) 725.121,311.648 ; 724.733,312.837 ccw(c724.263,313.307) 724.927,313.307 ccw(c725.591,313.307) 725.121,312.837 ; 724.733,318.348 cw(c724.263,317.879) 724.927,317.879 cw(c725.591,317.879) 725.121,318.348 ; 724.927,318.943 724.927,312.243 724.927,310.716 ; 725.465,342.265 cw(c725.984,342.265) v1@725.617,342.632 ; v1@725.465,342.72 725.465,336.116 725.884,335.697 731.46,335.697 ; v1(726.481,343.101) 726.481,339.037 727.116,338.402 731.434,338.402 ; 728.133,312.837 ccw(c727.663,313.307) 728.327,313.307 ccw(c728.991,313.307) 728.521,312.837 ; 728.133,318.348 cw(c727.663,317.879) 728.327,317.879 cw(c728.991,317.879) 728.521,318.348 ; 728.327,312.243 728.327,318.943 ; 731.089,332.341 ccw(c730.192,331.445) 730.192,332.712 ccw(c730.192,333.98) 731.089,333.084 ; 731.089,335.326 ccw(c730.192,334.429) 730.192,335.697 ccw(c730.192,336.964) 731.089,336.068 ; 732.392,310.912 cw(c733.976,309.327) 733.976,311.568 ccw(c733.976,310.86) 733.476,311.361 ; 733.16,311.68 cw(c733.976,310.864) 733.976,312.018 ; 733.339,321.13 ccw(c732.467,322.003) 733.701,322.003 ; 733.519,311.404 ccw(c733.08,311.843) 733.701,311.843 ; 733.723,312.243 731.688,310.208 ; 733.781,312.837 ccw(c733.312,313.307) 733.976,313.307 ccw(c734.64,313.307) 734.17,312.837 ; 733.781,318.348 cw(c733.312,317.879) 733.976,317.879 cw(c734.64,317.879) 734.17,318.348 ; 733.781,322.997 ccw(c733.312,323.467) 733.976,323.467 ccw(c734.64,323.467) 734.17,322.997 ; 733.781,328.508 cw(c733.312,328.039) 733.976,328.039 cw(c734.64,328.039) 734.17,328.508 ; 733.976,318.943 733.976,312.243 733.976,311.861 732.323,310.208 731.688,310.208 ; 733.976,329.103 733.976,322.403 733.976,321.767 732.704,320.495 720.385,320.495 719.177,319.287 719.177,318.943 719.177,312.243 719.177,310.651 718.422,309.896 674.088,309.896 673.933,310.051 673.933,310.462 ; 737.181,312.837 ccw(c736.712,313.307) 737.376,313.307 ccw(c738.04,313.307) 737.57,312.837 ; 737.181,318.348 cw(c736.712,317.879) 737.376,317.879 cw(c738.04,317.879) 737.57,318.348 ; 737.181,319.537 ccw(c736.712,320.007) 737.376,320.007 ccw(c738.04,320.007) 737.57,319.537 ; 737.181,321.808 cw(c736.712,321.339) 737.376,321.339 cw(c738.04,321.339) 737.57,321.808 ; 737.181,322.997 ccw(c736.712,323.467) 737.376,323.467 ccw(c738.04,323.467) 737.57,322.997 ; 737.181,328.508 cw(c736.712,328.039) 737.376,328.039 cw(c738.04,328.039) 737.57,328.508 ; 737.181,329.697 ccw(c736.712,330.167) 737.376,330.167 ccw(c738.04,330.167) 737.57,329.697 ; 541.922,394.65 542.181,394.91 542.791,394.91 ; 542.111,396.239 542.671,396.799 542.671,396.822 ; 542.671,395.91 542.671,396.314 ; 542.671,396.314 542.671,396.822 ; 548.005,310.716 564.007,310.716 ; 564.007,310.716 564.642,310.716 564.828,310.902 564.828,312.243 ; 583.027,310.208 583.027,310.716 ; 583.027,310.208 589.788,310.208 ; 683.822,394.65 684.081,394.91 684.691,394.91 ; 684.011,396.239 684.571,396.799 684.571,396.822 ; 684.571,395.91 684.571,396.314 ; 684.571,396.314 684.571,396.822 ; 689.905,310.716 705.907,310.716 ; 705.907,310.716 706.542,310.716 706.728,310.902 706.728,312.243 ; 724.927,310.208 724.927,310.716 ; 724.927,310.208 731.688,310.208
  Top Layer w0.6: 607.06,393.139 607.06,392.25 607.631,391.679 611.632,391.679 ; 748.96,393.139 748.96,392.25 749.531,391.679 753.532,391.679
